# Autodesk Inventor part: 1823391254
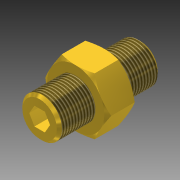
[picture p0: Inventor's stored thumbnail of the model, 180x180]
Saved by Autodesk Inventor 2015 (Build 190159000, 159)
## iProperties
Created: 2013-02
Part Number: 1823391254
Material: Generic
Document SubType Name: Modeling
Designer: Marci
Density: 1 g/cm^3
Appearance: Glossy - Gold
Translation Standard: STEP AP214IS
FileName: 1823391254
PreProcessor: PRO/ENGINEER BY PARAMETRIC TECHNOLOGY CORPORATION, 2009380
PostProcessor: Build: 160, Release: 2012 RTM - Date: Tue 03/01/2011
Sent Units: millimeter
Uncertainty: 0.001
Author: Marci
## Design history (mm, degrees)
node "18233912541"
thread "Thread1" dims "d0" = 10, "d1" = 0
thread "Thread2" dims "d2" = 10, "d3" = 0
node "1823391254"
node "Base1"
